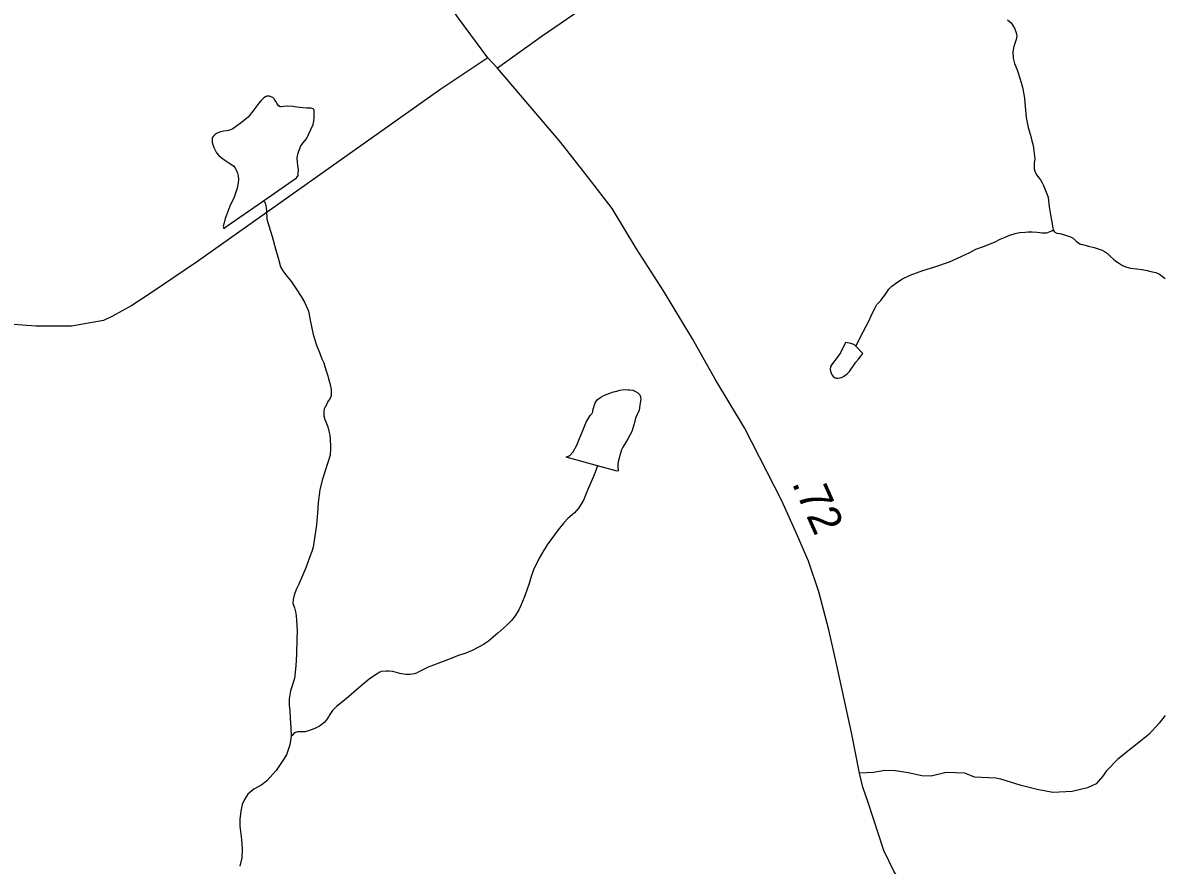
# Model space of a CAD drawing. Extents: x 2220236 to 2384410, y 720751 to 894131.
# Drawn here: x 2284074 to 2288550, y 826230 to 829540 of the extents above; entities that cross this region are included whole.
import ezdxf

# ---------------------------------------------------------------- set-up
doc = ezdxf.new("R2010")
doc.units = 0
for name, color, linetype in [('Exist Hydrographic Creek Single Shore', 7, 'Continuous'), ('Exist Hydrographic Misc Water Feature', 7, 'Continuous'), ('Exist Hydrographic Pond Under 1500 Sq Ft', 7, 'Continuous'), ('Exist Road Non-System Type 51', 7, 'Continuous'), ('Exist Road Primary NC Attributed', 7, 'Continuous'), ('Exist Road Primary NC Service Mileage Hundredths English Label', 7, 'Continuous'), ('Exist Road Secondary Type 51 Attributed', 7, 'Continuous')]:
    doc.layers.add(name, color=color, linetype=linetype)

msp = doc.modelspace()

# ---------------------------------------------------------------- linework, layer by layer
at = {"layer": 'Exist Hydrographic Creek Single Shore'}
for points in [[(2287942.2, 829551.5), (2287956.7, 829539.7), (2287969.4, 829518.1), (2287976.9, 829499.9), (2287978.9, 829487.4), (2287977, 829473.7), (2287973.2, 829462.3), (2287967.3, 829446), (2287963.6, 829425.4), (2287965, 829400.1), (2287969.8, 829379.4), (2287980.1, 829355.5), (2287992.5, 829318.2), (2288001, 829286.2), (2288009, 829244.1), (2288011.6, 829210.6), (2288015.9, 829167.8), (2288024, 829128.3), (2288032.2, 829098.6), (2288038.6, 829076.2), (2288042.9, 829058.1), (2288049.3, 829004.8), (2288047.3, 828988.4), (2288047.1, 828978.6), (2288047.5, 828966.1), (2288049.9, 828956.2), (2288055.9, 828942.3), (2288072.2, 828922.3), (2288078.8, 828911.4), (2288084.2, 828900.7), (2288092.3, 828880.9), (2288102.6, 828855.1), (2288105, 828827.2), (2288107.2, 828809.1), (2288111.3, 828785.4), (2288115.5, 828764.6), (2288120.1, 828734.4), (2288122.2, 828726.8)], [(2288122.2, 828726.8), (2288126, 828719.5), (2288127.9, 828716.8), (2288135.7, 828713.4), (2288147.8, 828711.5), (2288162.9, 828707.9), (2288174.6, 828704.4), (2288189.6, 828699.1), (2288200.6, 828693.3), (2288212.2, 828681.6), (2288222.2, 828673.9), (2288229, 828670.5), (2288236.5, 828668), (2288246.3, 828666.2), (2288260.3, 828662.6), (2288282.5, 828656.2), (2288294.5, 828652.7), (2288313.8, 828646.7), (2288324.1, 828640.6), (2288334.8, 828633.2), (2288346.7, 828621.4), (2288358.6, 828611.4), (2288368, 828603), (2288378.3, 828596.2), (2288394.2, 828586.7), (2288410.8, 828579.1), (2288426.1, 828575.5), (2288448.7, 828572.4), (2288471.3, 828570.3), (2288491.2, 828566.6), (2288506.2, 828563), (2288525.1, 828558.7), (2288539.1, 828552.5), (2288561.4, 828535)]]:
    msp.add_lwpolyline(points, dxfattribs=at)
at = {"layer": 'Exist Hydrographic Misc Water Feature'}
for points in [[(2285019.2, 828840.3), (2285024.4, 828834.6), (2285028.4, 828821.4), (2285030.6, 828800.7), (2285032.8, 828768.8), (2285041.1, 828737.5), (2285053.7, 828699.5), (2285066.2, 828651.7), (2285078.4, 828611.1), (2285086.7, 828581.4), (2285094.9, 828565.8), (2285106.7, 828549.9), (2285129.1, 828521.5), (2285147.5, 828494.2), (2285167.6, 828464.3), (2285179.9, 828442.7), (2285196.2, 828406.3), (2285202.4, 828370.8), (2285215, 828314.7), (2285227.2, 828272.8), (2285239.8, 828244.7), (2285248.1, 828218.9), (2285256, 828203.4), (2285260.3, 828189.2), (2285266.2, 828172.6), (2285272.3, 828152.8), (2285274.7, 828141.3), (2285279.9, 828123.2), (2285285, 828099.4), (2285284.8, 828091.2), (2285284.9, 828081.4), (2285285.1, 828074.8), (2285281.3, 828063.4), (2285275.2, 828055.4), (2285271.5, 828048.9), (2285265.3, 828036.5), (2285261.6, 828031), (2285257.5, 828022.9), (2285255.9, 828012.1), (2285255.9, 827995.1), (2285259.9, 827980.9), (2285264.3, 827972), (2285272.1, 827952.8), (2285276.3, 827934.6), (2285279.6, 827919.2), (2285281.3, 827905), (2285281.7, 827894.5), (2285282.8, 827883), (2285283.1, 827867.3), (2285281.3, 827841.1), (2285271.8, 827812.7), (2285259.9, 827775.3), (2285250, 827742.7), (2285240.7, 827705.1), (2285234.7, 827654.4), (2285231.3, 827614.1), (2285228, 827566.7), (2285218.6, 827506.2), (2285214.1, 827480), (2285208.8, 827462.1), (2285200.8, 827438.6), (2285191, 827412.6), (2285185.5, 827398), (2285157.9, 827333.6), (2285148.3, 827313.5), (2285140.3, 827291.3), (2285136.3, 827273.4), (2285134.7, 827258), (2285140.9, 827241.5), (2285147, 827220), (2285149.1, 827193.7), (2285151.5, 827150.1), (2285149.9, 827119.9), (2285148.6, 827057.6), (2285147, 827013.4), (2285141.4, 826963.3), (2285125.6, 826915.4), (2285120.4, 826883.4), (2285120.2, 826857.2), (2285122.4, 826837.4), (2285124.7, 826807.2), (2285127.2, 826769.4), (2285127.5, 826737.3), (2285127.5, 826736.6)], [(2287346.9, 828268.9), (2287360.2, 828294.2), (2287367.8, 828310.5), (2287376, 828325.7), (2287387.6, 828348.4), (2287397.2, 828367.9), (2287407.1, 828388.4), (2287417.1, 828410.1), (2287424.9, 828424.7), (2287429, 828432.8), (2287434.7, 828438.6), (2287444.8, 828448.9), (2287450.5, 828457), (2287460.6, 828469.3), (2287476.2, 828493.5), (2287487.9, 828505.4), (2287502.2, 828515), (2287527.8, 828531.8), (2287559.6, 828547.6), (2287609.6, 828566.2), (2287657.4, 828580.6), (2287715.2, 828600.1), (2287760.9, 828622.1), (2287794.7, 828637.8), (2287818.6, 828650.4), (2287848.6, 828660.3), (2287878.4, 828672.8), (2287894.6, 828679), (2287914.2, 828689.4), (2287932.7, 828697.3), (2287952.2, 828705.7), (2287972.4, 828711.8), (2287989.8, 828715.8), (2288011.9, 828717.6), (2288023.4, 828719), (2288039.7, 828718), (2288058.4, 828716.6), (2288069.9, 828715.7), (2288077.7, 828714.6), (2288088.9, 828714.4), (2288096.7, 828714.2), (2288104, 828716.7), (2288116.2, 828722), (2288122.2, 828726.8)], [(2286331.9, 827799), (2286321.5, 827770.3), (2286315.6, 827756.6), (2286301.5, 827724.8), (2286290.1, 827696.5), (2286276.3, 827664), (2286258.6, 827633.8), (2286240.8, 827613.9), (2286215.1, 827591.5), (2286199, 827575.4), (2286177.4, 827547), (2286134.3, 827488.8), (2286116.2, 827458), (2286102.7, 827436.4), (2286096.8, 827424), (2286089, 827410.4), (2286080.7, 827389.9), (2286071, 827363.9), (2286063.2, 827336.2), (2286053.5, 827310.1), (2286044, 827281.8), (2286030.3, 827249.9), (2286022.4, 827233.7), (2286008.8, 827209.4), (2285994.3, 827191.6), (2285974.9, 827173.3), (2285939.5, 827141.9), (2285903.7, 827110.8), (2285883.7, 827096.5), (2285839.6, 827073.5), (2285814.2, 827063.5), (2285786.1, 827053.3), (2285736.2, 827034.6), (2285666.1, 827007.5), (2285642.6, 826996.5), (2285630.3, 826989.3), (2285620.7, 826984.5), (2285612.7, 826981.4), (2285596, 826979.5), (2285578.9, 826979.8), (2285554.7, 826983.6), (2285528, 826990.7), (2285511, 826992.7), (2285500.8, 826992.9), (2285482.7, 826990.7), (2285476.8, 826988.5), (2285458.8, 826977.4), (2285435.2, 826960.5), (2285403.5, 826934.3), (2285373.8, 826909.3), (2285343.7, 826883.7), (2285306, 826853.3), (2285290.3, 826837.2), (2285280.2, 826822.7), (2285274.7, 826812.9), (2285266.6, 826801), (2285257.5, 826790.3), (2285248.8, 826782.3), (2285238.8, 826776), (2285220.9, 826766.5), (2285199.8, 826758.7), (2285191.2, 826756.6), (2285183.3, 826754.2), (2285177.1, 826753.6), (2285162.3, 826753.9), (2285153.1, 826754.1), (2285145.2, 826751.7), (2285139.2, 826747.9), (2285133.5, 826741.4), (2285127.5, 826736.6)], [(2285127.5, 826736.6), (2285123.5, 826702.9), (2285109.3, 826663.9), (2285096, 826641.2), (2285068.6, 826601.7), (2285032.7, 826562.1), (2285013.3, 826546.1), (2284981.5, 826528.1), (2284958.1, 826508.9), (2284944.3, 826488.5), (2284935.3, 826468.4), (2284930.2, 826442.9), (2284926.2, 826409.5), (2284926.7, 826383.3), (2284933.1, 826331.3), (2284935.3, 826293.6), (2284933.9, 826259.2), (2284926.4, 826225.9)]]:
    msp.add_lwpolyline(points, dxfattribs=at)
at = {"layer": 'Exist Hydrographic Pond Under 1500 Sq Ft'}
for points in [[(2285019.2, 828840.3), (2285149.4, 828930.4), (2285155.5, 828940.1), (2285155.2, 828945.7), (2285157.3, 828963.7), (2285154.9, 828977.9), (2285153, 828994.3), (2285151.6, 829006.5), (2285152.5, 829017.9), (2285156.4, 829032), (2285165.3, 829053.1), (2285174.2, 829066.7), (2285188.3, 829084.4), (2285214.1, 829140.6), (2285217, 829153.7), (2285218.6, 829169.1), (2285219.1, 829178.9), (2285219, 829190.4), (2285218.1, 829195.3), (2285216.9, 829198.6), (2285214.3, 829201.3), (2285211.1, 829203), (2285206.5, 829203.8), (2285201, 829204.9), (2285188.8, 829204.1), (2285173.7, 829205.4), (2285150.8, 829208.2), (2285134.8, 829210.2), (2285115.2, 829211.6), (2285099.7, 829210.2), (2285088.9, 829209.5), (2285084.3, 829209.6), (2285078.8, 829214), (2285075, 829219.6), (2285071.5, 829223.9), (2285069, 829229.6), (2285064.5, 829235.6), (2285060.7, 829241.2), (2285056.2, 829245.6), (2285048.7, 829249), (2285042.5, 829251.4), (2285032.7, 829251), (2285026.7, 829248.5), (2285020.4, 829244.7), (2285008.7, 829233.4), (2285001, 829224.4), (2284981.7, 829197.9), (2284959.5, 829168.9), (2284927.8, 829143.9), (2284899.5, 829123.2), (2284889.6, 829119.5), (2284881.6, 829117), (2284874.4, 829115.5), (2284861.9, 829113.5), (2284846.1, 829109.6), (2284834.8, 829104.2), (2284828.1, 829099.4), (2284822.1, 829093), (2284818.1, 829087.2), (2284817.3, 829083.9), (2284817.5, 829078.3), (2284818.3, 829069.1), (2284821.7, 829057.6), (2284824.5, 829049.3), (2284834.6, 829029.4), (2284843.2, 829019.4), (2284852.9, 829011), (2284867.1, 829000.2), (2284887.2, 828987.4), (2284901.1, 828978.2), (2284907.8, 828968.9), (2284913.5, 828959.9), (2284917.5, 828949), (2284919.3, 828938.5), (2284920.9, 828924.3), (2284919.4, 828910.6), (2284916, 828890), (2284904.1, 828854.2), (2284886.6, 828819.4), (2284871, 828777.8), (2284869.2, 828771.2), (2284864.9, 828753.3), (2284861.4, 828741.2), (2284863.5, 828731.4), (2284871.5, 828737.7), (2285019.2, 828840.3)], [(2287346.9, 828268.9), (2287341.1, 828274), (2287338.5, 828275.6), (2287326.5, 828280.2), (2287306.2, 828283.9), (2287286.7, 828243.3), (2287268.8, 828219), (2287255, 828201.3), (2287249.2, 828193.2), (2287247.2, 828189), (2287246.3, 828177.5), (2287247.5, 828170.9), (2287251.2, 828158.7), (2287254.3, 828153.7), (2287257.8, 828149.4), (2287261.7, 828147), (2287265.6, 828145.3), (2287269.9, 828143.6), (2287277.7, 828143.4), (2287285.3, 828144.9), (2287293.5, 828147), (2287297.5, 828149.6), (2287303.8, 828153.4), (2287312.5, 828160.7), (2287321.6, 828169.4), (2287346.9, 828205.9), (2287357, 828217.9), (2287366.4, 828230.1), (2287374.5, 828239.8), (2287366.8, 828248.2), (2287356.2, 828259.9), (2287348.5, 828268.2), (2287346.9, 828268.9)], [(2286331.9, 827799), (2286209, 827833.3), (2286222.9, 827839.6), (2286236.6, 827853.4), (2286250.3, 827880), (2286258.2, 827899.5), (2286273.8, 827937.9), (2286281.7, 827958.1), (2286288.9, 827972.7), (2286303.2, 827996.3), (2286309.6, 828002.8), (2286312.7, 828010.9), (2286313.2, 828018.1), (2286322.9, 828046.8), (2286330.7, 828058.7), (2286344.7, 828069.3), (2286358.7, 828077.2), (2286380.5, 828084.9), (2286394.3, 828089.6), (2286407.8, 828092.6), (2286419.4, 828096.3), (2286428.3, 828097.7), (2286440.4, 828098.4), (2286451.9, 828098.2), (2286458.5, 828098.1), (2286470.6, 828096.2), (2286480.3, 828091.7), (2286490.4, 828085.9), (2286497.4, 828077.6), (2286500.5, 828070), (2286501.3, 828059.5), (2286499.4, 828046.4), (2286495.2, 828017.6), (2286481.4, 827986.1), (2286475.7, 827963.9), (2286465.9, 827933.9), (2286450.2, 827905.4), (2286442, 827889.2), (2286430.8, 827872.3), (2286426.3, 827861.6), (2286422.1, 827848.6), (2286419.7, 827840.4), (2286416.8, 827829), (2286412.9, 827815.3), (2286411, 827802.9), (2286411.1, 827791.4), (2286413.3, 827784.8), (2286412.5, 827779.9), (2286409.5, 827777.7), (2286331.9, 827799)]]:
    msp.add_lwpolyline(points, dxfattribs=at)
at = {"layer": 'Exist Road Non-System Type 51'}
for points in [[(2285900.7, 829402.3), (2285715.7, 829278.5), (2284760.5, 828601.9), (2284577.8, 828478.1), (2284502.2, 828429.5), (2284426.8, 828386.9), (2284390.8, 828370.4), (2284265.2, 828347.3), (2284125.2, 828348), (2283985.3, 828358.7), (2283915.1, 828360.1), (2283869.2, 828355.7), (2283821.4, 828341.1), (2283755.8, 828304.7), (2283597, 828195.2), (2283561.2, 828156.7), (2283421.5, 827937.5), (2283326.7, 827792.7), (2283287.1, 827746.3), (2283273.4, 827720.2)], [(2288561.7, 826818.4), (2288538.1, 826788.1), (2288498.3, 826743.7), (2288375.4, 826646.7), (2288331.8, 826600.2), (2288315.9, 826578.2), (2288290.4, 826549.9), (2288256.4, 826533.6), (2288196.6, 826519.1), (2288120.7, 826516.2), (2288058.6, 826527.7), (2287996.5, 826543.2), (2287916.2, 826568.3), (2287896.3, 826572.1), (2287812.2, 826575.4), (2287774.2, 826591), (2287702, 826594.3), (2287642.4, 826579.7), (2287606.4, 826581.5), (2287552.3, 826593), (2287502.2, 826600.5), (2287460.3, 826602.1), (2287416.3, 826593.6), (2287360.5, 826591.9)]]:
    msp.add_lwpolyline(points, dxfattribs=at)
at = {"layer": 'Exist Road Primary NC Attributed'}
msp.add_line((2285938.2, 829361.7), (2285900.7, 829402.3), dxfattribs=at)
for points in [[(2285900.7, 829402.3), (2285785.1, 829557.2), (2285462.9, 830016), (2285317.1, 830226.4), (2285248.5, 830347.9), (2285174.4, 830484.7), (2285139.7, 830570.5), (2285087.6, 830714.2), (2285049.3, 830881), (2285033.1, 830957.5), (2285006.5, 831122.1), (2284978.7, 831400.2), (2284950.9, 831706.2), (2284930.1, 832125.7), (2284902.3, 832445.6), (2284894.1, 832665.8), (2284882.6, 832867.4), (2284875.6, 833013.4), (2284875.6, 833154.8), (2284886, 833416.7), (2284898.8, 833551.2), (2284910.4, 833639.2)], [(2287620.5, 826022.7), (2287558.7, 826112.3), (2287497.8, 826204.6), (2287457.2, 826288.1), (2287395.2, 826476), (2287374.4, 826536.3), (2287360.5, 826591.9), (2287330.4, 826744.9), (2287270.1, 827020.7), (2287240, 827155.2), (2287201.8, 827303.5), (2287160.1, 827424), (2287113.8, 827533), (2287056.4, 827661.9), (2286909.8, 827948.4), (2286794, 828139.2), (2286704.5, 828298.2), (2286590.9, 828487.1), (2286485.3, 828652.1), (2286388.8, 828810.1), (2286296.1, 828930.6), (2286187.2, 829069.7), (2285938.2, 829361.7)]]:
    msp.add_lwpolyline(points, dxfattribs=at)
at = {"layer": 'Exist Road Secondary Type 51 Attributed'}
msp.add_lwpolyline([(2288722.5, 830645.8), (2288166.6, 830636.5), (2287886.3, 830636.5), (2287733.4, 830634.2), (2287668.5, 830622.6), (2287615.3, 830608.7), (2287527.2, 830569.3), (2287464.7, 830529.9), (2287392.9, 830471.9), (2287212.2, 830293.5), (2287021.1, 830132.4), (2286932, 830065.7), (2286522.9, 829770), (2286284.5, 829603.8), (2286114.3, 829486.9), (2285938.2, 829361.7)], dxfattribs=at)

# ---------------------------------------------------------------- texts
at = {"layer": 'Exist Road Primary NC Service Mileage Hundredths English Label'}
msp.add_text('.72', height=125, rotation=293.9712, dxfattribs=at).set_placement((2287093.9, 827731.4))

doc.saveas('drawing.dxf')
